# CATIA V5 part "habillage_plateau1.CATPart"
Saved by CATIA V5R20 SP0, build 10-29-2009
Part number: habillage_plateau1
Bounding box of the stored display mesh (mm): x 0 to 105, y -400 to -40, z -59.902 to 105
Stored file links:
  C:\Users\Noëllie\Documents\IFMA\2A\S3\IAO\Projet Artobolevski\Catia\habillage_plateau1.CATPart
  C:\Users\Noëllie\Documents\IFMA\2A\S3\IAO\Projet Artobolevski\Catia\assemblage_balance.CATProduct
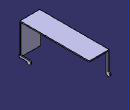
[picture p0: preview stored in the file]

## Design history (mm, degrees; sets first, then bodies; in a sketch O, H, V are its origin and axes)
Set1
  Plane1 "Plan_horizontal_plateau1": linked copy from another document
  Point1 "B2g": linked copy from another document
  Point2: linked copy from another document
  Point3 "pp_12": linked copy from another document
  Point4: linked copy from another document
  Plane2 "plan_vertical_plateau1": linked copy from another document
  Point5 "pp_21": linked copy from another document
  Point6 "pp_13": linked copy from another document
  Plane3 "plan_plateau1_bielle": linked copy from another document
  Point7 "C1": linked copy from another document
  Plane4 "plan_plateau1_support2": linked copy from another document
  Point8 "pp_11": linked copy from another document
Body1 (main body)
  Sketch1 on Plane1, origin (0, 0, 100), H (1, 0, 0), V (0, 1, 0)
    point P1 (0, -50)
    line L1 (0, -50) -> (100, -50)
    line L2 (100, -50) -> (100, -400)
    line L3 (100, -400) -> (0, -400)
    line L4 (0, -400) -> (0, -50)
    point P2 (100, -50)
    point P3 (100, -400)
    point P4 (0, -400)
    reference projected point E1 (0, -50) from Point1
    reference projected point E2 (100, -50) from Point2
    reference projected point E3 (100, -400) from Point3
    reference projected point E4 (0, -400) from Point4
    horizontal: L1 H, L3 H
    vertical: L2 V, L4 V
    coincidence: P1 E1, E2 P2, P3 E3, E4 P4
  Pad1: profile Sketch1, direction (0, 0, 1), length 5
  Sketch2 on Plane2, origin (0, -400, 0), H (-1, 0, 0), V (0, 0, 1)
    point P1 (0, 100)
    line L1 (0, 100) -> (-100, 100)
    line L2 (-100, 100) -> (-100, -50)
    line L3 (-100, -50) -> (0, -50)
    line L4 (0, -50) -> (0, 100)
    point P3 (-100, -50)
    reference projected point E1 (0, 100) from Point4
    reference projected point E2 (-100, 100) from Point5
    reference projected point E3 (-100, -50) from Point6
    horizontal: L1 H, L3 H
    vertical: L2 V, L4 V
    coincidence: P1 E1, L2 E2, P3 E3
  Pad2: profile Sketch2, direction (0, 1, 0), length 5
  Sketch3 on Plane3, origin (100, 0, 0), H (0, 1, 0), V (0, 0, 1)
    line L1 (-400, -40) -> (-350, -40)
    line L2 (-358.3333, -55.5277) -> (-362, -50)
    line L3 (-362, -50) -> (-400, -50)
    point P5 (-400, -50)
    line L4 (-400, -40) -> (-400, -50)
    arc A1 centre (-350, -50) radius 10 from (-350, -40) to (-358.3333, -55.5277) cw
    point P6 (-350, -50)
    reference projected point E1 (-350, -50) from Point7
    reference projected point E2 (-400, -50) from Point6
    length L3 = 38
    length L4 = 10
    horizontal: L1 H, L3 H
    vertical: L4 V
    tangency: A1 L1, L2 A1
    coincidence: P6 E1, P5 E2
  Pad3: profile Sketch3, direction (1, 0, 0), length 5
  Sketch4 on Plane4, origin (0, 0, 0), H (0, 1, 0), V (0, 0, 1)
    line L1 (-50, 100) -> (-50, 10)
    point P1 (-50, 100)
    line L2 (-50, 100) -> (-60, 100)
    line L3 (-60, 100) -> (-60, 0)
    reference projected point E1 (-50, 100) from Point8
    arc A1 centre (-50, 0) radius 10 from (-50, 10) to (-60, 0) cw
    point P5 (-50, 0)
    reference projected point E2 (-50, 0) from Point1
    length L2 = 10
    vertical: L1 V, L3 V
    horizontal: L2 H
    coincidence: P1 E1, P5 E2
    tangency: A1 L3
  Pad4: profile Sketch4, direction (1, 0, 0), length 5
